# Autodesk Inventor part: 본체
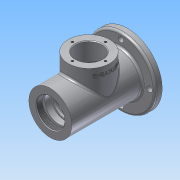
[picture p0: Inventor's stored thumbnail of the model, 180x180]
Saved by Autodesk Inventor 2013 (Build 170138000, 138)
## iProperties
Created: 2016-08
Part Number: 본체
Material: 알루미늄 6061
Document SubType Name: Modeling
Designer: Administrator
Density: 2.71 g/cm^3
Mass: 731.263 g
Surface Area: 615.627 cm^2
Volume: 269.839 cm^3
Author: Administrator
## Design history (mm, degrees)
sketch "스케치1"
  geometry: L1 (-57.5, 0)-(57.5, 0); L2 (-57.5, 0)-(-57.5, 31); L3 (-57.5, 31)-(44.5, 31); L4 (44.5, 31)-(44.5, 50); L5 (44.5, 50)-(54.5, 50); L6 (54.5, 50)-(54.5, 31); L7 (54.5, 31)-(57.5, 31); L8 (57.5, 31)-(57.5, 0); 2 further points
  constraints: 16 end point, 6 perpendicular, 1 coincident, 1 collinear, 1 horizontal, 1 midpoint, 1 parallel
  dimensions: "d0" = 100 diameter of L5 L1; "d2" = 115 distance of L1.start L1.end; "d4" = 3 horizontal distance of L7.end L5.end; "d6" = 13 distance between parallel lines of L8 L4; "d7" = 62 diameter of L3 L1
revolve "회전1" sketch "스케치1" stored, may be unused: angle "d8" = 90 deg
node "작업 평면1"
sketch "스케치2"
  geometry: L1 (57.5, 31)-(57.5, -31) reference; C1 r 30 at (1.5, 0); 1 further point
  constraints: 1 centre point, 1 horizontal alignment
  dimensions: "d10" = 60 diameter of C1; "d12" = 56 distance from line of L1 C1.centre
extrude "돌출1" join sketch "스케치2" stored distance "d13" = 10; taper "d14" = 0 deg
sketch "스케치3"
  geometry: L1 (57.5, 0)-(-48.5, 0); L2 (57.5, -31)-(57.5, 31) reference; L3 (57.5, 0)-(57.5, 21); L4 (57.5, 21)-(43.5, 16); L5 (43.5, 16)-(43.5, 12.5); L6 (43.5, 12.5)-(36.2, 12.5); L7 (36.2, 12.5)-(36.2, 10); L8 (36.2, 10)-(33.5, 10); L9 (33.5, 10)-(33.5, 16.5); L10 (33.5, 16.5)-(28.5, 16.5); L11 (28.5, 16.5)-(28.5, 17.5); L12 (28.5, 17.5)-(17.5, 17.5); L13 (17.5, 17.5)-(17.5, 26); L14 (17.5, 26)-(-20.5, 26); L15 (-20.5, 26)-(-20.5, 17.5); L16 (-20.5, 17.5)-(-31.5, 17.5); L17 (-31.5, 17.5)-(-31.5, 18.5); L18 (-31.5, 18.5)-(-33.25, 18.5); L19 (-33.25, 18.5)-(-33.25, 17.5); L20 (-33.25, 17.5)-(-36.5, 17.5); L21 (-36.5, 17.5)-(-36.5, 20); L22 (-36.5, 20)-(-45.5, 20); L23 (-45.5, 20)-(-45.5, 24); L24 (-45.5, 24)-(-48.5, 24); L25 (-48.5, 24)-(-48.5, 0); L26 (-57.5, -31)-(-57.5, 31) reference; L27 (-31.5, 49)-(28.5, 49) reference; 3 further points
  constraints: 48 end point, 15 perpendicular, 7 parallel, 3 midpoint, 2 collinear, 2 point on line, 1 horizontal, 1 vertical alignment
  dimensions: "d15" = 42 diameter of L3.end L1; "d17" = 32 diameter of L4.end L1; "d18" = 25 diameter of L6 L1; "d19" = 20 diameter of L8 L1; "d20" = 33 diameter of L10 L1; "d21" = 35 diameter of L12 L1; "d22" = 52 diameter of L14 L1; "d23" = 37 diameter of L18 L1; "d24" = 1.75 distance of L17.end L18.end; "d25" = 3 distance of L23.end L24.end; "d26" = 12 distance between parallel lines of L23 L26; "d27" = 21 distance from line of L26 L21.end; "d28" = 26 distance from line of L26 L17.end; "d29" = 40 diameter of L22 L1; "d30" = 48 diameter of L24 L1; "d31" = 14 distance between parallel lines of L3 L5; "d32" = 7.3 distance of L5.end L6.end; "d33" = 5 distance from line of L11.end L9; "d34" = 38 distance of L13.end L14.end; "d36" = 2.7 distance of L7.end L8.end
revolve "회전2" sketch "스케치3" stored, may be unused: angle "d37" = 90 deg
fillet "모깎기3" dims "d87" = 3
hole "구멍1" diameter "d40" = 38; stored, may be unused: countersink angle "d44" = 90 deg, drill point angle "d46" = 0 deg; dims "d38" = 10, "d39" = 10, "d41" = 6, "d42" = 4, "d43" = 2, "d45" = 50
hole "구멍2" diameter "d49" = 40.376; stored, may be unused: countersink angle "d53" = 90 deg, drill point angle "d55" = 0 deg; dims "d47" = 10, "d48" = 10, "d50" = 9, "d51" = 4, "d52" = 2, "d54" = 9
sketch "스케치4"
  geometry: C1 r 19 at (0, 0) reference; 2 further points
  constraints: 1 vertical alignment
  dimensions: "d56" = 24 distance of C1.centre point (0, 24)
hole "구멍3" sketch "스케치4" at (0, 24) diameter "d57" = 3.242; stored, may be unused: countersink angle "d61" = 90 deg, drill point angle "d63" = 118 deg; dims "d58" = 8, "d59" = 4, "d60" = 2, "d62" = 10
sketch "스케치5"
  geometry: 2 further points
  constraints: 1 horizontal alignment
  dimensions: "d67" = 41.5 distance of point (0, 0) point (-41.5, 0)
hole "구멍4" sketch "스케치5" at (-41.5, 0) diameter "d68" = 8; stored, may be unused: countersink angle "d72" = 90 deg, drill point angle "d74" = 0 deg; dims "d69" = 8, "d70" = 4, "d71" = 2, "d73" = 10
fillet "모깎기1" dims "d78" = 3
fillet "모깎기2" dims "d79" = 3
chamfer "모따기1" distance "d80" = 1; stored, may be unused: second distance "d81" = 2, angle "d82" = 45 deg
chamfer "모따기2" distance "d88" = 1; stored, may be unused: second distance "d89" = 2, angle "d90" = 45 deg
fillet "모깎기4" dims "d91" = 3
fillet "모깎기5" dims "d92" = 0.3
sketch "스케치6"
  geometry: L1 (42.8, 12.5)-(43.5, 12.904); L2 (43.5, 12.5)-(36.5, 12.5) reference; L3 (43.5, 13.886)-(43.5, -13.886) reference; L4 (43.5, 0)-(41.594, 0); L5 (42.8, 12.5)-(43.5, 12.5); L6 (43.5, 12.904)-(43.5, 12.5); 1 further point
  constraints: 8 end point, 2 perpendicular, 2 point on line, 1 midpoint, 1 parallel
  dimensions: "d93" = 30 deg angle of L2 L1; "d94" = 0.7 distance from line of L3 L1.start
revolve "회전3" sketch "스케치6" stored, may be unused: angle "d95" = 90 deg
fillet "모깎기6" dims "d96" = 3
node "작업 평면2"
sketch "스케치7" dims "d15" = 42, "d17" = 32, "d18" = 25, "d19" = 20, "d20" = 33, "d21" = 35, "d22" = 52, "d23" = 37, "d24" = 1.75, "d25" = 3, "d26" = 12, "d27" = 21, "d28" = 26, "d29" = 40, "d30" = 48, "d31" = 14, "d32" = 7.3, "d33" = 5, "d34" = 38, "d36" = 2.7
  geometry: L1 (-56, -80)-(-56, -18) reference; L2 (-30, 0)-(30, 0) reference; 2 further points
  constraints: 1 other
  dimensions: "d101" = 56 distance from line of L1 point (0, -10); "d102" = 10 distance from line of L2 point (0, -10)
feature "엠보싱1" sketch "스케치7" dims "d103" = 0.5, "d104" = 0
fillet "모깎기7" dims "d109" = 0.3
node "솔리드1"
pattern_circular "원형 패턴1" dims angle "d65" = 360 deg
pattern_circular "원형 패턴2" dims angle "d76" = 360 deg
other parameters: "d9" = 49
